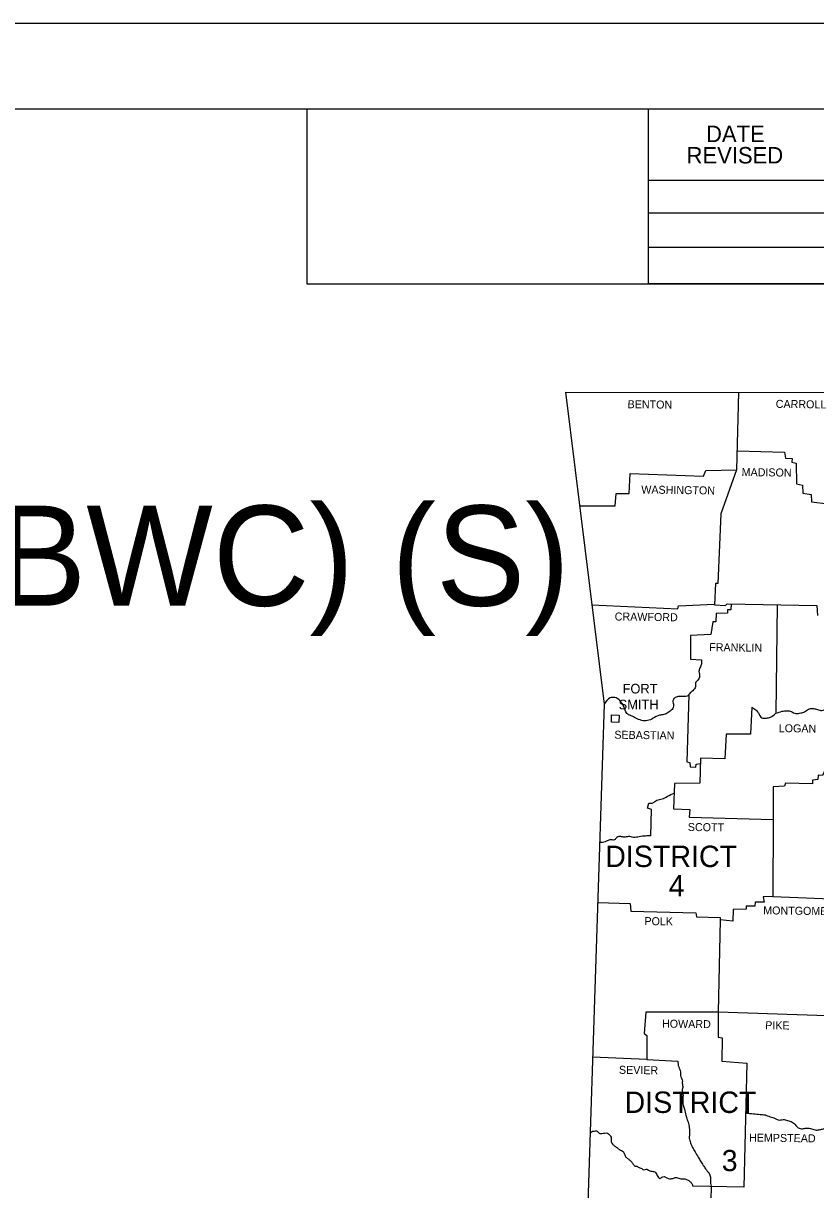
# Model space of a CAD drawing. Extents: x 840176 to 859715, y 1589036 to 1600368.
# Drawn here: x 851907 to 854218, y 1596633 to 1600036 of the extents above; entities that cross this region are included whole.
import ezdxf

# ---------------------------------------------------------------- set-up
doc = ezdxf.new("R2010")
doc.units = 0
for name, color, linetype in [('Default', 7, 'Continuous'), ('DSN_DRFT_Border', 7, 'Continuous'), ('SHET_Border-Text', 7, 'Continuous')]:
    doc.layers.add(name, color=color, linetype=linetype)

msp = doc.modelspace()

# ---------------------------------------------------------------- linework, layer by layer
at = {"layer": 'DSN_DRFT_Border'}
for p, q in [((853592.2, 1597646.2), (853588.2, 1597645.7)), ((853569.2, 1596803.7), (853560.1, 1596798))]:
    msp.add_line(p, q, dxfattribs=at)
for points in [[(840175.5, 1600035.6), (840175.5, 1589035.6), (857175.5, 1589035.6), (857175.5, 1600035.6)], [(853622.4, 1597997.2), (853623, 1598018.4), (853644.8, 1598017.7), (853644.2, 1597996.6)]]:
    msp.add_lwpolyline(points, close=True, dxfattribs=at)
for points in [[(853488.3, 1598959.8), (854373.4, 1598959.2), (855150.8, 1598960.7), (856067.3, 1598974.7), (856492.4, 1598984.7)], [(853488.3, 1598959.8), (853601.5, 1598049.5), (853552.4, 1596563.8)], [(853993.4, 1598959.4), (853987.6, 1598733)], [(853989.1, 1598788.7), (854127.2, 1598784.3), (854130.3, 1598766.8), (854149.3, 1598766.2), (854148.7, 1598755.6), (854161.4, 1598752.2), (854162.7, 1598692.1), (854179.8, 1598688.4), (854181, 1598664.7), (854204.7, 1598661.6), (854205.9, 1598639.5), (854253.3, 1598634.4), (854376.5, 1598637.7), (854377.4, 1598959.2)], [(853529.5, 1598628.3), (853633.9, 1598628), (853636.4, 1598663.8), (853674.1, 1598663.8), (853677.5, 1598722.3), (853891.3, 1598714.9), (853897.5, 1598731), (853987.6, 1598733), (853941.7, 1598604.7), (853932.7, 1598401.5), (853926.1, 1598401.2), (853923, 1598339.8), (853955.1, 1598337), (853960.1, 1598342), (854221.2, 1598337), (854224, 1598308.1)], [(853565.5, 1598339.3), (853816.6, 1598327.4), (853817.8, 1598336.4), (853923.1, 1598341.1)], [(853971.5, 1598341.8), (853971, 1598324.9), (853960.7, 1598324.9), (853961, 1598314.9), (853928, 1598314.3), (853927.4, 1598290.1), (853918.1, 1598290.1), (853912.8, 1598253.3), (853853.6, 1598250.2), (853853.3, 1598181.1), (853885.1, 1598178.6)], [(854106.3, 1598339.2), (854102.3, 1598023)], [(853847.9, 1598076.9), (853842.1, 1597881.7), (853850.8, 1597879.6), (853852.1, 1597866.5), (853868.9, 1597865.6), (853870.1, 1597874.6), (853882.1, 1597876.6)], [(854032, 1598040.5), (854028.2, 1597962.3), (853957, 1597961.7), (853952.9, 1597890.5), (853882.6, 1597892.3), (853880.4, 1597819.2), (853806.3, 1597818.3), (853803.8, 1597744.8), (853850.8, 1597742.3), (853849, 1597719.6), (854093.9, 1597712.9)], [(854391.7, 1597956.7), (854389.2, 1597878), (854264.7, 1597877.4), (854248.2, 1597863.4), (854238.6, 1597841.6), (854225.2, 1597842.2), (854224.6, 1597830.1), (854208.7, 1597828.2), (854209.3, 1597817), (854130, 1597818.9), (854126.9, 1597810.2), (854094.2, 1597808.9), (854093.9, 1597712.9)], [(853737.5, 1597665.5), (853739.4, 1597742.6), (853728.2, 1597746.4), (853731.9, 1597761)], [(854093.9, 1597712.9), (854093.3, 1597488.7), (854065.6, 1597488.1), (854068.1, 1597471.9), (854041.6, 1597472.2), (854041, 1597460.1), (854015.1, 1597460.1), (854015.8, 1597451.6), (853977.8, 1597450.4), (853976.9, 1597417.1), (853939.8, 1597420.5), (853933.6, 1597151)], [(853582.4, 1597471.6), (853676.9, 1597468.5), (853679.4, 1597445.4), (853868.6, 1597441.4), (853870.7, 1597429.6), (853939.8, 1597427.4), (853939.8, 1597420.5)], [(854093.3, 1597488.7), (854311.2, 1597480.2)], [(854251, 1597140.1), (853933.6, 1597151), (853722.9, 1597151.3), (853718.3, 1597088.8), (853725.7, 1597083.5), (853725.4, 1597013.2), (853567.5, 1597020.4)], [(853933.6, 1597151), (853933.6, 1597078.2), (853945.7, 1597076), (853944.5, 1597008.2), (854017.3, 1597002.3), (854008.3, 1596640.6), (853859.5, 1596644.1)], [(853725.4, 1597013.2), (853816, 1597008.2)]]:
    msp.add_lwpolyline(points, dxfattribs=at)
for points in [[(853885.1, 1598178.6), (853885.1, 1598167.1), (853880.7, 1598155.3), (853877.9, 1598144.7), (853879.8, 1598131), (853874.8, 1598120.1), (853867.6, 1598111.1), (853867.6, 1598100.5), (853859.5, 1598089), (853850.5, 1598080), (853843, 1598073.1), (853829, 1598072.2), (853817.5, 1598071.6), (853806.3, 1598067.5), (853802, 1598059.1), (853803.8, 1598046.7), (853799.5, 1598034.5), (853788.3, 1598025.5), (853775.5, 1598019.3), (853762.4, 1598017.1), (853744.1, 1598008.4), (853727.9, 1598001.6), (853710.2, 1598002.2), (853694, 1598009.3), (853679, 1598015.9), (853667.5, 1598022.7), (853658.5, 1598042.6), (853652.3, 1598053.8), (853641.7, 1598065), (853629.6, 1598069.4), (853619, 1598068.2), (853601.5, 1598049.5)], [(854032, 1598040.5), (854043.8, 1598033), (854053.1, 1598020.5), (854061.2, 1598010), (854075.2, 1598009.3), (854086.1, 1598011.5), (854102.3, 1598023)], [(854102.3, 1598023), (854120.6, 1598028.9), (854133.7, 1598030.5), (854147.1, 1598028), (854160.8, 1598022.4), (854175.1, 1598024), (854186, 1598027.7), (854197.2, 1598034.9), (854209, 1598037), (854220.9, 1598034.9), (854233, 1598031.4), (854245.8, 1598035.5), (854253.5, 1598042.3), (854266.6, 1598044.8), (854278.4, 1598044.8), (854286.5, 1598035.5), (854288.1, 1598025.2), (854298.7, 1598016.2), (854307.7, 1598010), (854310.8, 1597998.8), (854315.5, 1597990.4), (854320.4, 1597984.8), (854327.6, 1597981.6), (854339.7, 1597982.6), (854358.4, 1597978.8), (854370.2, 1597976.4), (854381.4, 1597966.7), (854391.7, 1597956.7)], [(853731.9, 1597761), (853743.8, 1597761.9), (853755.3, 1597769.4), (853770.5, 1597773.1), (853786.1, 1597780.9), (853805.4, 1597790.1)], [(853737.5, 1597665.5), (853722, 1597665.1), (853703.6, 1597663), (853687.1, 1597660.8), (853672.5, 1597663.6), (853659.1, 1597661.4), (853649.8, 1597663.6), (853638.3, 1597660.8), (853631.4, 1597653.9), (853617.7, 1597653.9), (853608.1, 1597649.6), (853592.2, 1597646.2)], [(853816, 1597008.2), (853818.8, 1596991.7), (853823.8, 1596977.1), (853824.1, 1596966.5), (853829.4, 1596950), (853829, 1596944.1), (853830.9, 1596931.6), (853828.7, 1596925.4), (853831.2, 1596912.3), (853830.9, 1596902.1), (853830.6, 1596894), (853831.5, 1596880.3), (853835.6, 1596868.1), (853839.9, 1596850.4), (853842.7, 1596840.7), (853847.4, 1596826.4), (853849.9, 1596809), (853850.5, 1596796.2), (853849.6, 1596784.1), (853853, 1596770.4), (853858.9, 1596756.7), (853866.4, 1596743.6), (853875.7, 1596728.7), (853882.3, 1596716.9), (853890.4, 1596704.4), (853896.9, 1596694.2), (853907.2, 1596680.8), (853911.5, 1596669.9), (853911.5, 1596654.9), (853913.7, 1596640.3), (853913.1, 1596624.8), (853912.1, 1596610.1), (853908.1, 1596590.8), (853910.6, 1596581.5), (853921.2, 1596567.8), (853927.7, 1596563.8), (853939.2, 1596561.6), (853944.5, 1596553.8), (853947.9, 1596542.6), (853959.4, 1596538.6), (853972.2, 1596537.6), (853978.4, 1596530.8), (853986.5, 1596522.1), (853991.5, 1596514.8)], [(854013.7, 1596856.9), (854036.6, 1596855.1), (854055.9, 1596852.9), (854070.5, 1596851.3), (854085.8, 1596846), (854099.8, 1596841.1), (854108.5, 1596837), (854123.1, 1596837.9), (854135.9, 1596835.5), (854149.9, 1596830.5), (854160.5, 1596821.1), (854167.3, 1596814), (854179.8, 1596811.2), (854190.4, 1596813), (854202.8, 1596811.8), (854216.8, 1596807.8), (854228.6, 1596808.1), (854238, 1596810.2), (854248.9, 1596812.7), (854262.3, 1596814.3), (854272.5, 1596811.8), (854286.2, 1596811.5), (854302.4, 1596812.7), (854324.4, 1596815.1)], [(853569.2, 1596803.7), (853581.3, 1596804), (853589.1, 1596796.9), (853594.4, 1596797.5), (853602.8, 1596798.7), (853611.5, 1596798.1), (853617.1, 1596793.1), (853622.1, 1596784.7), (853621.8, 1596776.3), (853622.1, 1596772.9), (853626.1, 1596766.1), (853632.7, 1596760.4), (853639.8, 1596755.2), (853646.1, 1596750.5), (853657.3, 1596743.6), (853658.5, 1596741.5), (853662.5, 1596732.4), (853668.1, 1596725.6), (853674.7, 1596720.9), (853681.8, 1596713.5), (853685, 1596710), (853690.6, 1596702.3), (853696.5, 1596701.6), (853705.2, 1596696.7), (853711.1, 1596695.1), (853717.3, 1596691), (853723.9, 1596693.2), (853732.3, 1596689.5), (853743.2, 1596686.7), (853749.4, 1596685.1), (853756.2, 1596674.9), (853763.7, 1596666.2), (853772.1, 1596671.1), (853788.9, 1596666.2), (853799.2, 1596665.8), (853808.5, 1596668.6), (853815.7, 1596667.7), (853828.7, 1596664.6), (853836.8, 1596664.6), (853845.9, 1596661.5), (853853.9, 1596654.9), (853859.2, 1596647.5), (853859.5, 1596644.1)]]:
    msp.add_spline(points, degree=3, dxfattribs=at)
at = {"layer": 'SHET_Border-Text'}
for p, q in [((853731, 1599276.2), (853731, 1599785.6)), ((853731, 1599578.4), (854727.5, 1599578.4)), ((853731, 1599276.2), (853731, 1599578.4)), ((853731, 1599482.4), (854727.5, 1599482.4)), ((853731, 1599382.4), (854727.5, 1599382.4)), ((854727.5, 1599276.2), (853731, 1599276.2))]:
    msp.add_line(p, q, dxfattribs=at)
for points in [[(840175.5, 1589035.6), (857175.5, 1589035.6), (857175.5, 1600035.6), (840175.5, 1600035.6)], [(840425.5, 1589285.6), (856925.5, 1589285.6), (856925.5, 1599785.6), (840425.5, 1599785.6)], [(852734.4, 1599276.2), (854727.5, 1599276.2), (854727.5, 1599124.6), (856925.5, 1599124.6), (856925.5, 1599785.6), (852734.4, 1599785.6)]]:
    msp.add_lwpolyline(points, close=True, dxfattribs=at)

# ---------------------------------------------------------------- texts
at = {"layer": 'Default'}
msp.add_text('PAVEMENT FRICTION IMPVTS. (UTBWC) (S)', height=292.209, dxfattribs=at).set_placement((845295.9, 1598336.7))
at = {"layer": 'DSN_DRFT_Border'}
for s, height, p in [('DATE', 48, (853898.5, 1599689.2)), ('REVISED', 48, (853841.7, 1599626.8)), ('FORT', 28.01, (853655.1, 1598080.9)), ('SMITH', 28.01, (853643.6, 1598034.5)), ('DISTRICT', 62.43, (853604.3, 1597574.5)), ('4', 62.4, (853789.5, 1597488.7)), ('DISTRICT', 62.43, (853660.7, 1596857.3)), ('3', 61.9, (853944.4, 1596687.5))]:
    msp.add_text(s, height=height, dxfattribs=at).set_placement(p)
for s, rotation, p in [('BENTON', 359.2874, (853669.6, 1598913.1)), ('CARROLL', 359.267, (854101.7, 1598914)), ('MADISON', 359.217, (854002.2, 1598715.2)), ('WASHINGTON', 359.2079, (853709.5, 1598664.1)), ('CRAWFORD', 359.2748, (853632.1, 1598293.8)), ('FRANKLIN', 359.1782, (853907.7, 1598204.5)), ('SEBASTIAN', 359.1959, (853630.9, 1597949)), ('LOGAN', 359.3076, (854110.5, 1597968)), ('SCOTT', 359.32, (853845.3, 1597679.8)), ('MONTGOMERY', 359.2707, (854065.1, 1597436.7)), ('POLK', 359.3233, (853718.7, 1597405.3)), ('HOWARD', 359.303, (853770, 1597106.2)), ('PIKE', 359.1737, (854071.1, 1597101.6)), ('SEVIER', 359.1815, (853644.3, 1596971.5)), ('HEMPSTEAD', 359.2571, (854023.8, 1596773.9))]:
    msp.add_text(s, height=23.34, rotation=rotation, dxfattribs=at).set_placement(p)

doc.saveas('drawing.dxf')
